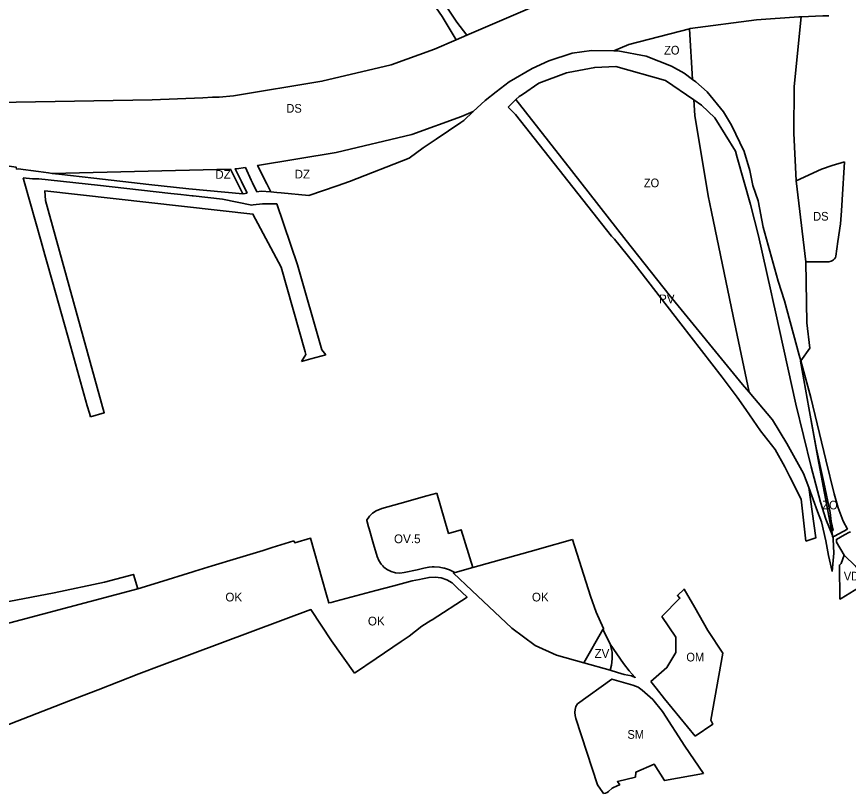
# Model space of a CAD drawing. Extents: x -650971 to -642489, y -1074311 to -1062745.
# Drawn here: x -648968 to -647822, y -1070124 to -1069053 of the extents above; entities that cross this region are included whole.
import ezdxf

# ---------------------------------------------------------------- set-up
doc = ezdxf.new("R2010")
doc.units = 0
doc.header["$LTSCALE"] = 4.8
for name, color, linetype, lineweight in [('11', 7, 'Continuous', 35), ('12', 7, 'Continuous', 35), ('13', 7, 'Continuous', 35), ('15', 7, 'Continuous', 35), ('18', 7, 'Continuous', 35), ('24', 7, 'Continuous', 35), ('25', 7, 'Continuous', 35), ('35', 7, 'Continuous', 35), ('40', 7, 'Continuous', 35), ('42', 7, 'Continuous', 35), ('62', 7, 'Continuous', 35)]:
    doc.layers.add(name, color=color, linetype=linetype, lineweight=lineweight)

msp = doc.modelspace()

# ---------------------------------------------------------------- linework, layer by layer
at = {"layer": '11'}
for points in [[(-648464.45, -1069730.89), (-648439.8, -1069724.19), (-648402.68, -1069713.53), (-648388.631, -1069709.738)], [(-648388.631, -1069709.738), (-648402.68, -1069713.53), (-648439.8, -1069724.19), (-648464.45, -1069730.89)], [(-648388.631, -1069709.738), (-648372.639, -1069765.241), (-648355.015, -1069760.287), (-648339.05, -1069812.45), (-648363.68, -1069819.31)], [(-648339.05, -1069812.45), (-648355.015, -1069760.287), (-648372.639, -1069765.241), (-648388.631, -1069709.738)], [(-648363.68, -1069819.31), (-648364.66, -1069818.68), (-648371.21, -1069815.56), (-648378.1, -1069813.29), (-648379.35, -1069813.05), (-648385.21, -1069811.91), (-648392.45, -1069811.44), (-648395.12, -1069811.6), (-648399.13, -1069811.85), (-648399.68, -1069811.88), (-648406.84, -1069813.23), (-648415.99, -1069815.59), (-648433.97, -1069819.3), (-648439.89, -1069819.97), (-648445.8, -1069819.51), (-648451.53, -1069817.98), (-648455.44, -1069816.09), (-648456.88, -1069815.39), (-648461.64, -1069811.86), (-648463.32, -1069810.04), (-648464.34, -1069808.93), (-648465.67, -1069807.49), (-648468.82, -1069802.44), (-648470.97, -1069796.9), (-648476.1, -1069780.3), (-648482.2, -1069758.8), (-648482.98, -1069756.08), (-648485.44, -1069747.39), (-648485.14, -1069746.55), (-648483.59, -1069744.24), (-648481.79, -1069741.57), (-648477.39, -1069737.44), (-648472.4, -1069734.1), (-648464.45, -1069730.89)], [(-648464.45, -1069730.89), (-648472.4, -1069734.1), (-648477.39, -1069737.44), (-648481.79, -1069741.57), (-648483.59, -1069744.24), (-648485.14, -1069746.55), (-648485.44, -1069747.39), (-648482.98, -1069756.08), (-648482.2, -1069758.8), (-648476.1, -1069780.3), (-648470.97, -1069796.9)], [(-648470.97, -1069796.9), (-648468.82, -1069802.44), (-648465.67, -1069807.49), (-648464.34, -1069808.93), (-648463.32, -1069810.04), (-648461.64, -1069811.86), (-648456.88, -1069815.39), (-648455.44, -1069816.09), (-648451.53, -1069817.98), (-648445.8, -1069819.51), (-648439.89, -1069819.97), (-648433.97, -1069819.3), (-648415.99, -1069815.59), (-648406.84, -1069813.23), (-648399.68, -1069811.88), (-648399.13, -1069811.85), (-648395.12, -1069811.6), (-648392.45, -1069811.44), (-648385.21, -1069811.91), (-648379.35, -1069813.05), (-648378.1, -1069813.29), (-648371.21, -1069815.56), (-648364.66, -1069818.68), (-648363.68, -1069819.31), (-648339.05, -1069812.45)]]:
    msp.add_lwpolyline(points, dxfattribs=at)
at = {"layer": '12'}
for points in [[(-648078.54, -1069880.01), (-648053.61, -1069854.64), (-648057.11, -1069851.12), (-648048.08, -1069841.95), (-648032.94, -1069867.46), (-648015.11, -1069898.98), (-647994.71, -1069930.53)], [(-648093.67, -1069969.42), (-648071.58, -1069950.39), (-648059.5, -1069929.52), (-648059.32, -1069908.27), (-648078.54, -1069880.01)], [(-647994.71, -1069930.53), (-648010.94, -1070022.65), (-648010.44, -1070023.66), (-648008.18, -1070028.25), (-648032.85, -1070044.73)], [(-648032.85, -1070044.73), (-648074.96, -1069993.46), (-648086.55, -1069978.57), (-648093.67, -1069969.42)]]:
    msp.add_lwpolyline(points, dxfattribs=at)
at = {"layer": '13'}
msp.add_line((-648363.68, -1069819.31), (-648339.05, -1069812.45), dxfattribs=at)
for points in [[(-648800.85, -1069841.52), (-648772.48, -1069832.83), (-648725.21, -1069818.38), (-648722.24, -1069817.54), (-648698.31, -1069810.16), (-648665.05, -1069799.99), (-648627.99, -1069788.67), (-648615.88, -1069784.93), (-648586.091, -1069775.75)], [(-648586.091, -1069775.75), (-648584.65, -1069778.1), (-648562.87, -1069771.85), (-648546.97, -1069828.68), (-648541.06, -1069849.78), (-648537.86, -1069861.22), (-648534.57, -1069860.45), (-648528.11, -1069858.73), (-648472.97, -1069844.09), (-648447.98, -1069837.44), (-648422.75, -1069830.78)], [(-648339.05, -1069812.45), (-648251.94, -1069787.95), (-648247.27, -1069786.64), (-648201.83, -1069773.86)], [(-648201.83, -1069773.86), (-648176.78, -1069851.74), (-648169.15, -1069873.81), (-648159.1, -1069896.39), (-648158.79, -1069896.95), (-648160.04, -1069897.73), (-648186.268, -1069943.697)], [(-648422.75, -1069830.78), (-648412.74, -1069828.72), (-648408.45, -1069827.83), (-648399.4, -1069825.97), (-648391.08, -1069825.45), (-648382.8, -1069826.55), (-648374.89, -1069829.22), (-648367.64, -1069833.35), (-648361.3, -1069839.7), (-648347.06, -1069853), (-648395.03, -1069884.22)], [(-648186.268, -1069943.697), (-648223.99, -1069932.96), (-648253.13, -1069919.7), (-648285.62, -1069895.71), (-648340.38, -1069843.78), (-648365.81, -1069819.9), (-648363.68, -1069819.31)], [(-649048.918, -1070055.852), (-649037.411, -1070011.659), (-649032.644, -1069990.371), (-649028.007, -1069957.455), (-649027.135, -1069928.902), (-649028.017, -1069902.109), (-648800.85, -1069841.52)], [(-648502.048, -1069957.969), (-648533.79, -1069913.49), (-648562.242, -1069870.301), (-648767.83, -1069946.87), (-648799.32, -1069959.08), (-648855.72, -1069980.96), (-648878.623, -1069989.839), (-648896.48, -1069996.77), (-649048.918, -1070055.852)], [(-648395.03, -1069884.22), (-648396.87, -1069885.43), (-648409.44, -1069893.25), (-648426.82, -1069906.88), (-648438.08, -1069914.49), (-648472.6, -1069937.81), (-648502.048, -1069957.969)]]:
    msp.add_lwpolyline(points, dxfattribs=at)
at = {"layer": '15'}
msp.add_line((-648290.39, -1069177.69), (-648280.1, -1069166.97), dxfattribs=at)
for points in [[(-648362.06, -1069084.664), (-648381.44, -1069052.48), (-648415.29, -1069003.16), (-648419.78, -1068994.25), (-648427.21, -1068980.13), (-648461.22, -1068915.44), (-648488.09, -1068854.16), (-648521.92, -1068750.34), (-648537.29, -1068681.95), (-648557.4, -1068599.9)], [(-648541.25, -1068592.3), (-648541.89, -1068618.64), (-648514.35, -1068741.53), (-648486.25, -1068831.83), (-648451.76, -1068910.91), (-648409.15, -1068988.44), (-648361.43, -1069060.64), (-648347.522, -1069078.405), (-648362.06, -1069084.664)], [(-648280.1, -1069166.97), (-648203.01, -1069264.73), (-648127.77, -1069361.38), (-648068.71, -1069436.57), (-647967.53, -1069559.94), (-647958.34, -1069570.698)], [(-647909.25, -1069673.35), (-647922.32, -1069649.56), (-647942.48, -1069623.82), (-647962.93, -1069594.39), (-647974.74, -1069577.39), (-647980.21, -1069569.97), (-647984.36, -1069564.49), (-647995.61, -1069549.95), (-648052.62, -1069476.32), (-648116.93, -1069393.25), (-648143.81, -1069359.39), (-648147.81, -1069355.26), (-648280.46, -1069187.61), (-648290.39, -1069177.69)], [(-648959.11, -1069275.13), (-648945.96, -1069276.64), (-648937.2, -1069276.37), (-648856.68, -1069285.01), (-648755.56, -1069296.7), (-648741.58, -1069298.16), (-648725.82, -1069299.81), (-648724.82, -1069299.92), (-648684.39, -1069304.67), (-648643.83, -1069312.66), (-648641.98, -1069312.45), (-648629.16, -1069310.91), (-648609.304, -1069310.668)], [(-648866.17, -1069604.48), (-648867.62, -1069599.37), (-648870.76, -1069589.26), (-648893.86, -1069506.89), (-648918.65, -1069418.53), (-648927.38, -1069387.623), (-648927.37, -1069387.62), (-648929.16, -1069381.32), (-648934.38, -1069362.79), (-648957.74, -1069280), (-648959.11, -1069275.13)], [(-648575.148, -1069528.347), (-648569.22, -1069518.4), (-648570.288, -1069514.714), (-648603.386, -1069398.357), (-648642.241, -1069324.949), (-648929.112, -1069293.123), (-648928.347, -1069306.125), (-648847.097, -1069598.995), (-648866.17, -1069604.48)], [(-648609.304, -1069310.668), (-648581.051, -1069394.771), (-648547.3, -1069512.136), (-648541.88, -1069518.95)], [(-648541.88, -1069518.95), (-648562.46, -1069524.76), (-648575.148, -1069528.347)], [(-647958.34, -1069570.698), (-647925.99, -1069608.57), (-647906.16, -1069641.48), (-647883.51, -1069682.71), (-647875.82, -1069701.85), (-647866.4, -1069771.43), (-647879.96, -1069776.1)], [(-647879.96, -1069776.1), (-647886.43, -1069718.16), (-647902.18, -1069687.23), (-647909.25, -1069673.35)], [(-649069.4, -1069760.67), (-649058.34, -1069783.72), (-649049.22, -1069801.23), (-649029.61, -1069835.47), (-649010.55, -1069865.09), (-648916.03, -1069847.12), (-648846.934, -1069832.583), (-648806.946, -1069821.79), (-648800.85, -1069841.52), (-649028.017, -1069902.109)], [(-648150.006, -1069954.019), (-648148, -1069947), (-648147, -1069938), (-648147, -1069929), (-648149.67, -1069917.83)], [(-648149.67, -1069917.83), (-648131.5, -1069944.75), (-648123.45, -1069954.79), (-648115.23, -1069963.75), (-648120.68, -1069961.63), (-648130.36, -1069959.62), (-648139.78, -1069956.93), (-648150.006, -1069954.019)]]:
    msp.add_lwpolyline(points, dxfattribs=at)
at = {"layer": '18'}
for points in [[(-648159.02, -1070123.71), (-648159.89, -1070122.49), (-648167.48, -1070111.75), (-648182.01, -1070067.11), (-648197.23, -1070020.37), (-648198.22, -1070016.4), (-648198.48, -1070012.3), (-648198.17, -1070008.05), (-648197.19, -1070003.94), (-648194.84, -1070000.49), (-648147.46, -1069966.19), (-648140.96, -1069968.01), (-648128.48, -1069971.7), (-648118.75, -1069974.53), (-648111.44, -1069977.32)], [(-648111.44, -1069977.32), (-648105.79, -1069981.56), (-648091.06, -1069994.07), (-648077.68, -1070011.06), (-648046.83, -1070058.62), (-648021.35, -1070096.14)], [(-648021.35, -1070096.14), (-648074.76, -1070106.17), (-648089.22, -1070083.27), (-648114.7, -1070094.68), (-648115.11, -1070101.26), (-648139.91, -1070107.48), (-648136.61, -1070111.97)], [(-648136.61, -1070111.97), (-648139.45, -1070112.79), (-648147.02, -1070116.35), (-648152.35, -1070121.05), (-648153.85, -1070122.38), (-648156.07, -1070123.54), (-648159.02, -1070123.71)]]:
    msp.add_lwpolyline(points, dxfattribs=at)
at = {"layer": '24'}
for points in [[(-648347.522, -1069078.405), (-648156.739, -1068996.273), (-648058.764, -1068970.927), (-648038.746, -1068968.301), (-648038.596, -1068968.284), (-648038.596, -1068968.284), (-648038.596, -1068968.281)], [(-647886.615, -1069053.052), (-647889.927, -1069053.218), (-647948.18, -1069057.276), (-648039.666, -1069069.279), (-648040.705, -1069069.547)], [(-647848.615, -1069051.679), (-647856.541, -1069051.548), (-647886.615, -1069053.052)], [(-648040.705, -1069069.547), (-648124.327, -1069091.181), (-648144.866, -1069099.987)], [(-648698.04, -1069163.983), (-648688.912, -1069163.603), (-648668.959, -1069161.838), (-648547.243, -1069141.81), (-648451.865, -1069119.456), (-648392.002, -1069097.554), (-648362.06, -1069084.664), (-648347.522, -1069078.405)], [(-648144.866, -1069099.987), (-648175.65, -1069099.64), (-648202.46, -1069103.3), (-648234.22, -1069113.6), (-648257.5, -1069124.41), (-648289.25, -1069142.79), (-648306.83, -1069156.57), (-648322.14, -1069168.56), (-648338.522, -1069183.389)], [(-649125.864, -1069172.018), (-649076.02, -1069172.683), (-648781.015, -1069167.44), (-648711.546, -1069164.545), (-648698.04, -1069163.983)], [(-648338.522, -1069183.389), (-648354.978, -1069190.492), (-648423.173, -1069215.44), (-648527.693, -1069239.938), (-648635.818, -1069257.857), (-648622.995, -1069283.455), (-648617.434, -1069294.508)], [(-648918.889, -1069268.875), (-648924.13, -1069268.21), (-648937.91, -1069266.51), (-648965.8, -1069262.75), (-648968.05, -1069263.06), (-648968.49, -1069260.36), (-649001.3, -1069255.92), (-649056.95, -1069252.55), (-649139.63, -1069248.73), (-649165.62, -1069249.43), (-649202.63, -1069254.4), (-649220.18, -1069257.03), (-649242.5, -1069263.3), (-649267.5, -1069270.41), (-649319.72, -1069292.47), (-649322.22, -1069293.54)], [(-647893.553, -1069279.017), (-647858.37, -1069263.03), (-647843.873, -1069257.994), (-647826.928, -1069253.199)], [(-647826.928, -1069253.199), (-647830.23, -1069305.38), (-647831.19, -1069320.69), (-647832.29, -1069338.58), (-647836.2, -1069362.68), (-647838.79, -1069382.86), (-647839.4, -1069384.73), (-647840.42, -1069386.51), (-647841.81, -1069387.99), (-647843.41, -1069389.23), (-647845.25, -1069390.07), (-647848.24, -1069390.65), (-647880.326, -1069390.832), (-647893.553, -1069279.017)], [(-648656.242, -1069297.116), (-648673.267, -1069262.895), (-648918.889, -1069268.875)], [(-648636.85, -1069294.49), (-648642.755, -1069281.898), (-648644.51, -1069278.16), (-648652.716, -1069260.657), (-648665.007, -1069262.694), (-648666.827, -1069262.738), (-648665.1, -1069266.53), (-648658.18, -1069280.27), (-648650.58, -1069295.34), (-648650.06, -1069296.39)], [(-648650.06, -1069296.39), (-648655.53, -1069297.18), (-648656.242, -1069297.116)], [(-648617.434, -1069294.508), (-648630.82, -1069293.63), (-648636.85, -1069294.49)]]:
    msp.add_lwpolyline(points, dxfattribs=at)
at = {"layer": '25'}
for points in [[(-648040.705, -1069069.547), (-648039.666, -1069069.279), (-647948.18, -1069057.276), (-647889.927, -1069053.218), (-647886.615, -1069053.052)], [(-647886.615, -1069053.052), (-647896.362, -1069149.171), (-647896.67, -1069213.573), (-647893.553, -1069279.017), (-647880.326, -1069390.832)], [(-647887.087, -1069527.229), (-647889.22, -1069519.32), (-647909.67, -1069444.46), (-647918.08, -1069417.43), (-647938.77, -1069343.17), (-647945.63, -1069306.95), (-647953.01, -1069285.73), (-647957.56, -1069264.74), (-647965.06, -1069238.95), (-647982.58, -1069202.33), (-647993.8, -1069184.11), (-648016.36, -1069156.54), (-648031.92, -1069142.67), (-648036.291, -1069139.458), (-648040.705, -1069069.547)], [(-648034.421, -1069167.61), (-648024.02, -1069174.7), (-648005.47, -1069192.09), (-647977.29, -1069238.21), (-647974.81, -1069246.86), (-647956.27, -1069311.58), (-647945.28, -1069355.1), (-647928.41, -1069431.03), (-647925.16, -1069445.68), (-647922.04, -1069459.71), (-647893.75, -1069587.08), (-647872.87, -1069673.56), (-647859.722, -1069722.428), (-647852.78, -1069745.71), (-647843.443, -1069768.293)], [(-647958.34, -1069570.698), (-647980.331, -1069465.915), (-648010.092, -1069322.087), (-648015, -1069300), (-648033, -1069189), (-648034.421, -1069167.61)], [(-648617.434, -1069294.508), (-648622.995, -1069283.455), (-648635.818, -1069257.857), (-648527.693, -1069239.938), (-648423.173, -1069215.44), (-648354.978, -1069190.492), (-648338.522, -1069183.389)], [(-648338.522, -1069183.389), (-648351.77, -1069195.88), (-648355.81, -1069198.88), (-648389.91, -1069221.86), (-648407.73, -1069233.88), (-648427.08, -1069247.75), (-648508.95, -1069280.01), (-648526.15, -1069286.21), (-648565.18, -1069299.46), (-648603.228, -1069295.53), (-648609.425, -1069295.033), (-648617.434, -1069294.508)], [(-648918.889, -1069268.875), (-648673.267, -1069262.895), (-648656.242, -1069297.116)], [(-648656.242, -1069297.116), (-648730.66, -1069290.43), (-648785.92, -1069284.2), (-648861.49, -1069275.34), (-648909.86, -1069270.02), (-648918.889, -1069268.875)], [(-647880.326, -1069390.832), (-647878.93, -1069475.09), (-647874.75, -1069509.84), (-647887.087, -1069527.229)], [(-647875.82, -1069701.85), (-647883.51, -1069682.71), (-647906.16, -1069641.48), (-647925.99, -1069608.57), (-647958.34, -1069570.698)], [(-647876.056, -1069592.232), (-647865.69, -1069647.32), (-647855.158, -1069695.232), (-647846.484, -1069736.663), (-647845.086, -1069748.753), (-647842.438, -1069760.647), (-647844.371, -1069761.991), (-647843.449, -1069768.251)], [(-647843.449, -1069768.251), (-647862.266, -1069668.613), (-647876.056, -1069592.232)], [(-647843.74, -1069817.63), (-647848.71, -1069795.69), (-647852.63, -1069775.7), (-647858.44, -1069749.43), (-647864.19, -1069735.12), (-647875.82, -1069701.85)], [(-647843.443, -1069768.293), (-647843.337, -1069769.013), (-647842.798, -1069770.477), (-647842.54, -1069770.346)], [(-647842.54, -1069770.346), (-647842.489, -1069773.282), (-647841.402, -1069792.351), (-647843.74, -1069817.63)]]:
    msp.add_lwpolyline(points, dxfattribs=at)
at = {"layer": '35'}
for points in [[(-647831.62, -1069854.99), (-647833.172, -1069855.944), (-647833.91, -1069808.91), (-647831.32, -1069806.56), (-647827.16, -1069795.32)], [(-647827.16, -1069795.32), (-647811.83, -1069810.39), (-647789.55, -1069829.12), (-647831.62, -1069854.99)]]:
    msp.add_lwpolyline(points, dxfattribs=at)
at = {"layer": '40'}
msp.add_line((-648186.268, -1069943.697), (-648160.04, -1069897.73), dxfattribs=at)
for points in [[(-648160.04, -1069897.73), (-648157.81, -1069902.06), (-648149.67, -1069917.83)], [(-648149.67, -1069917.83), (-648147, -1069929), (-648147, -1069938), (-648148, -1069947), (-648150.006, -1069954.019), (-648186.268, -1069943.697)]]:
    msp.add_lwpolyline(points, dxfattribs=at)
at = {"layer": '42'}
for points in [[(-648144.866, -1069099.987), (-648124.327, -1069091.181), (-648040.705, -1069069.547), (-648036.291, -1069139.458)], [(-648036.291, -1069139.458), (-648048.06, -1069130.81), (-648065.16, -1069121.12), (-648100.37, -1069107.1), (-648139.27, -1069100.05), (-648144.866, -1069099.987)], [(-648280.1, -1069166.97), (-648275.19, -1069162.87), (-648270.92, -1069159.99), (-648248.14, -1069144.65), (-648209.89, -1069130.36), (-648207.77, -1069129.95), (-648171.14, -1069122.83), (-648141.92, -1069121.66), (-648073.66, -1069140.86), (-648034.421, -1069167.61)], [(-647958.34, -1069570.698), (-647967.53, -1069559.94), (-648068.71, -1069436.57), (-648127.77, -1069361.38), (-648203.01, -1069264.73), (-648280.1, -1069166.97)], [(-648034.421, -1069167.61), (-648033, -1069189), (-648015, -1069300), (-648010.092, -1069322.087), (-647980.331, -1069465.915), (-647958.34, -1069570.698)], [(-647876.056, -1069592.232), (-647887.649, -1069528.021), (-647887.087, -1069527.229)], [(-647887.087, -1069527.229), (-647873.43, -1069577.87), (-647852.44, -1069664.03)], [(-647843.449, -1069768.251), (-647844.371, -1069761.991), (-647842.438, -1069760.647), (-647845.086, -1069748.753), (-647846.484, -1069736.663), (-647855.158, -1069695.232), (-647865.69, -1069647.32), (-647876.056, -1069592.232)], [(-647852.44, -1069664.03), (-647841.26, -1069710.69), (-647835.76, -1069730.01), (-647828.61, -1069748.41), (-647822.54, -1069759.29)], [(-647842.54, -1069770.346), (-647842.798, -1069770.477), (-647843.337, -1069769.013), (-647843.443, -1069768.293), (-647843.449, -1069768.251)], [(-647822.54, -1069759.29), (-647840.49, -1069769.3), (-647842.55, -1069769.78), (-647842.54, -1069770.346)], [(-647827.16, -1069795.32), (-647837.93, -1069777.45), (-647838, -1069773.63), (-647826.95, -1069767.48), (-647820.09, -1069763.65), (-647818.73, -1069763.53)], [(-647789.55, -1069829.12), (-647811.83, -1069810.39), (-647827.16, -1069795.32)]]:
    msp.add_lwpolyline(points, dxfattribs=at)

# ---------------------------------------------------------------- texts
at = {"layer": '62', "width": 0.95}
for s, p in [('ZO', (-648075.473, -1069105.058)), ('DS', (-648596.118, -1069185.225)), ('ZO', (-648103.473, -1069288.058)), ('DS', (-647870.044, -1069334.044)), ('ZO', (-647857.423, -1069732.188)), ('VD', (-647827.767, -1069830.204)), ('OM', (-648044.853, -1069941.852)), ('SM', (-648126.077, -1070048.464))]:
    msp.add_text(s, height=12, dxfattribs=at).set_placement(p)
at = {"layer": '62'}
for s, p in [('DZ', (-648694.171, -1069276.367)), ('DZ', (-648584.843, -1069275.949)), ('PV', (-648082.5, -1069447.958)), ('OV.5', (-648447.819, -1069778.742)), ('OK', (-648680.267, -1069859.087)), ('OK', (-648257.724, -1069859.087)), ('OK', (-648483.81, -1069892.185)), ('ZV', (-648171.5, -1069936.875))]:
    msp.add_text(s, height=12, dxfattribs=at).set_placement(p)

doc.saveas('drawing.dxf')
